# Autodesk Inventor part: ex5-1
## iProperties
Shininess: 64.0
Length Units: 11272
Angle Units: 11279
Time Units: 11290
Mass Units: 11286
Length Display Precision: 3
Angle Display Precision: 2
Compacted: True
Part Number: ex5-1
Document SubType Name: Modeling
Created: 2003-11
Designer: Elise Moss
Cost Center: 0 lbmass
Authority: 0.97 in^3
Manufacturer: Standard
Standards Organization: Custom
Density: 0.0
Volumn: 0.0
Area: 0.0
PropertySet Name: Model Information
Control State: 0
Master: False
Checked Out: False
SaveDate: 2003-11-14
SaveTime: 19:15
TotalMass: 0 lbmass
TotalVolume: 0.97 in^3
Author: Elise Moss
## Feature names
1. Revolution1
2. Shell1
